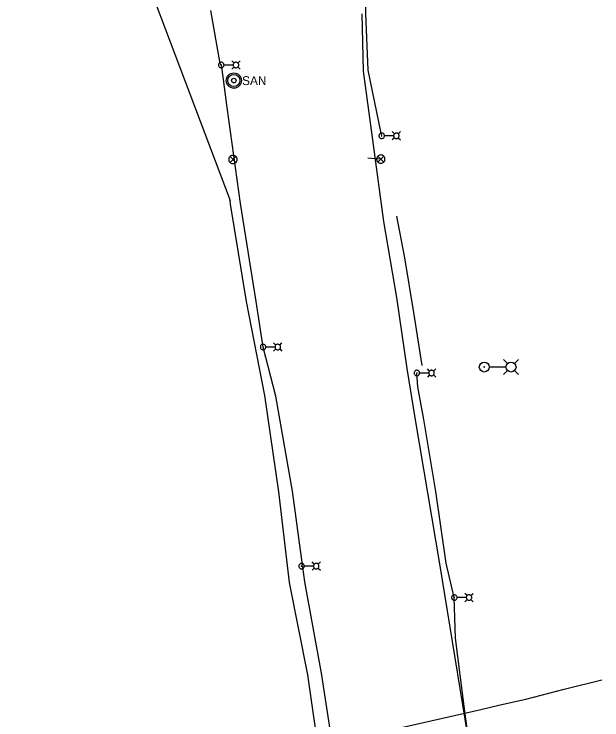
# Model space of a CAD drawing. Extents: x 600849 to 606371, y 330010 to 403088.
# Drawn here: x 604365 to 604830, y 336784 to 337341 of the extents above; entities that cross this region are included whole.
import ezdxf

# ---------------------------------------------------------------- set-up
doc = ezdxf.new("R2010")
doc.units = 0
for name, color, linetype in [('E_FTMS_Conduit', 7, 'Continuous'), ('E_LTG', 7, 'Continuous'), ('E_LTG_CID', 7, 'Continuous'), ('E_SIG', 7, 'Continuous'), ('E_UTL_E_UG', 7, 'Continuous'), ('E_UTL_FO_UG_QWEST', 7, 'Continuous'), ('E_UTL_G_UG', 7, 'Continuous'), ('E_UTL_SAN', 7, 'Continuous')]:
    doc.layers.add(name, color=color, linetype=linetype)

msp = doc.modelspace()

# ---------------------------------------------------------------- linework, layer by layer
at = {"layer": 'E_FTMS_Conduit'}
for points in [[(604787.77, 336403.56), (604778.06, 336454.77), (604767.68, 336514.34), (604755.05, 336571.74), (604744.37, 336629.18), (604737.87, 336681.73), (604730.03, 336734.18), (604701.87, 336906.78), (604692.35, 336962.82), (604682.52, 337020.66), (604676.08, 337061.02), (604667.84, 337117.16), (604657.46, 337177.3), (604649.41, 337237.66), (604641.55, 337295.97), (604640.55, 337341.15)], [(604667.53, 337181.51), (604673.81, 337148.58), (604680.95, 337105.47), (604687.63, 337063.48)]]:
    msp.add_lwpolyline(points, dxfattribs=at)
at = {"layer": 'E_LTG'}
for points in [[(604531.31, 337300.78), (604531.27, 337301.19), (604531.15, 337301.59), (604530.96, 337301.95), (604530.7, 337302.28), (604530.39, 337302.55), (604530.03, 337302.76), (604529.64, 337302.89), (604529.23, 337302.95), (604528.82, 337302.93), (604528.42, 337302.83), (604528.04, 337302.66), (604527.71, 337302.42), (604527.42, 337302.12), (604527.2, 337301.78), (604527.04, 337301.39), (604526.96, 337300.99), (604526.96, 337300.57), (604527.04, 337300.17), (604527.2, 337299.78), (604527.42, 337299.43), (604527.71, 337299.13), (604528.04, 337298.89), (604528.42, 337298.72), (604528.82, 337298.62), (604529.23, 337298.61), (604529.64, 337298.66), (604530.03, 337298.8), (604530.39, 337299.01), (604530.7, 337299.28), (604530.96, 337299.6), (604531.15, 337299.97), (604531.27, 337300.37), (604531.31, 337300.78)], [(604539.21, 337302.3), (604537.43, 337304.08)], [(604542.91, 337300.78), (604542.87, 337301.19), (604542.75, 337301.59), (604542.56, 337301.95), (604542.31, 337302.28), (604542, 337302.55), (604541.64, 337302.76), (604541.25, 337302.89), (604540.84, 337302.95), (604540.42, 337302.93), (604540.02, 337302.83), (604539.65, 337302.66), (604539.31, 337302.42), (604539.02, 337302.12), (604538.8, 337301.78), (604538.65, 337301.39), (604538.57, 337300.99), (604538.57, 337300.57), (604538.65, 337300.17), (604538.8, 337299.78), (604539.02, 337299.43), (604539.31, 337299.13), (604539.65, 337298.89), (604540.02, 337298.72), (604540.42, 337298.62), (604540.84, 337298.61), (604541.25, 337298.66), (604541.64, 337298.8), (604542, 337299.01), (604542.31, 337299.28), (604542.56, 337299.6), (604542.75, 337299.97), (604542.87, 337300.37), (604542.91, 337300.78)], [(604542.26, 337302.3), (604544.03, 337304.08)], [(604529.3, 337300.78), (604529.29, 337300.81), (604529.28, 337300.84), (604529.27, 337300.87), (604529.25, 337300.89), (604529.23, 337300.91), (604529.2, 337300.93), (604529.17, 337300.94), (604529.14, 337300.94), (604529.11, 337300.94), (604529.08, 337300.94), (604529.05, 337300.92), (604529.02, 337300.9), (604529, 337300.88), (604528.98, 337300.85), (604528.97, 337300.83), (604528.96, 337300.79), (604528.96, 337300.76), (604528.97, 337300.73), (604528.98, 337300.7), (604529, 337300.68), (604529.02, 337300.65), (604529.05, 337300.63), (604529.08, 337300.62), (604529.11, 337300.61), (604529.14, 337300.61), (604529.17, 337300.62), (604529.2, 337300.63), (604529.23, 337300.64), (604529.25, 337300.66), (604529.27, 337300.69), (604529.28, 337300.72), (604529.29, 337300.75), (604529.3, 337300.78)], [(604538.52, 337300.78), (604531.34, 337300.78)], [(604539.21, 337299.26), (604537.43, 337297.48)], [(604542.26, 337299.26), (604544.03, 337297.48)], [(604658.04, 337244.87), (604658, 337245.28), (604657.88, 337245.68), (604657.69, 337246.04), (604657.44, 337246.37), (604657.12, 337246.64), (604656.76, 337246.85), (604656.37, 337246.98), (604655.96, 337247.04), (604655.55, 337247.02), (604655.15, 337246.92), (604654.77, 337246.75), (604654.44, 337246.51), (604654.15, 337246.21), (604653.93, 337245.87), (604653.77, 337245.48), (604653.69, 337245.08), (604653.69, 337244.66), (604653.77, 337244.26), (604653.93, 337243.87), (604654.15, 337243.52), (604654.44, 337243.22), (604654.77, 337242.98), (604655.15, 337242.81), (604655.55, 337242.71), (604655.96, 337242.7), (604656.37, 337242.75), (604656.76, 337242.89), (604657.12, 337243.1), (604657.44, 337243.37), (604657.69, 337243.69), (604657.88, 337244.06), (604658, 337244.46), (604658.04, 337244.87)], [(604665.94, 337246.39), (604664.16, 337248.17)], [(604669.64, 337244.87), (604669.6, 337245.28), (604669.48, 337245.68), (604669.29, 337246.04), (604669.04, 337246.37), (604668.73, 337246.64), (604668.37, 337246.85), (604667.98, 337246.98), (604667.57, 337247.04), (604667.15, 337247.02), (604666.75, 337246.92), (604666.38, 337246.75), (604666.04, 337246.51), (604665.75, 337246.21), (604665.53, 337245.87), (604665.38, 337245.48), (604665.3, 337245.08), (604665.3, 337244.66), (604665.38, 337244.26), (604665.53, 337243.87), (604665.75, 337243.52), (604666.04, 337243.22), (604666.38, 337242.98), (604666.75, 337242.81), (604667.15, 337242.71), (604667.57, 337242.7), (604667.98, 337242.75), (604668.37, 337242.89), (604668.73, 337243.1), (604669.04, 337243.37), (604669.29, 337243.69), (604669.48, 337244.06), (604669.6, 337244.46), (604669.64, 337244.87)], [(604668.99, 337246.39), (604670.77, 337248.17)], [(604656.03, 337244.87), (604656.02, 337244.9), (604656.02, 337244.93), (604656, 337244.96), (604655.98, 337244.98), (604655.96, 337245), (604655.93, 337245.02), (604655.9, 337245.03), (604655.87, 337245.03), (604655.84, 337245.03), (604655.81, 337245.03), (604655.78, 337245.01), (604655.75, 337244.99), (604655.73, 337244.97), (604655.71, 337244.94), (604655.7, 337244.92), (604655.69, 337244.88), (604655.69, 337244.85), (604655.7, 337244.82), (604655.71, 337244.79), (604655.73, 337244.77), (604655.75, 337244.74), (604655.78, 337244.72), (604655.81, 337244.71), (604655.84, 337244.7), (604655.87, 337244.7), (604655.9, 337244.71), (604655.93, 337244.72), (604655.96, 337244.73), (604655.98, 337244.75), (604656, 337244.78), (604656.02, 337244.81), (604656.02, 337244.84), (604656.03, 337244.87)], [(604665.25, 337244.87), (604658.07, 337244.87)], [(604665.94, 337243.35), (604664.16, 337241.57)], [(604668.99, 337243.35), (604670.77, 337241.57)], [(604564.33, 337078.06), (604564.29, 337078.48), (604564.17, 337078.87), (604563.99, 337079.24), (604563.73, 337079.57), (604563.42, 337079.84), (604563.06, 337080.04), (604562.67, 337080.18), (604562.26, 337080.24), (604561.85, 337080.22), (604561.44, 337080.12), (604561.07, 337079.95), (604560.73, 337079.71), (604560.44, 337079.41), (604560.22, 337079.06), (604560.07, 337078.68), (604559.99, 337078.27), (604559.99, 337077.86), (604560.07, 337077.45), (604560.22, 337077.07), (604560.44, 337076.72), (604560.73, 337076.42), (604561.07, 337076.18), (604561.44, 337076.01), (604561.85, 337075.91), (604562.26, 337075.89), (604562.67, 337075.95), (604563.06, 337076.09), (604563.42, 337076.29), (604563.73, 337076.56), (604563.99, 337076.89), (604564.17, 337077.26), (604564.29, 337077.65), (604564.33, 337078.06)], [(604572.24, 337079.59), (604570.46, 337081.37)], [(604575.93, 337078.06), (604575.89, 337078.48), (604575.78, 337078.87), (604575.59, 337079.24), (604575.33, 337079.57), (604575.02, 337079.84), (604574.66, 337080.04), (604574.27, 337080.18), (604573.86, 337080.24), (604573.45, 337080.22), (604573.05, 337080.12), (604572.67, 337079.95), (604572.33, 337079.71), (604572.05, 337079.41), (604571.82, 337079.06), (604571.67, 337078.68), (604571.59, 337078.27), (604571.59, 337077.86), (604571.67, 337077.45), (604571.82, 337077.07), (604572.05, 337076.72), (604572.33, 337076.42), (604572.67, 337076.18), (604573.05, 337076.01), (604573.45, 337075.91), (604573.86, 337075.89), (604574.27, 337075.95), (604574.66, 337076.09), (604575.02, 337076.29), (604575.33, 337076.56), (604575.59, 337076.89), (604575.78, 337077.26), (604575.89, 337077.65), (604575.93, 337078.06)], [(604575.28, 337079.59), (604577.06, 337081.37)], [(604562.32, 337078.06), (604562.32, 337078.1), (604562.31, 337078.13), (604562.29, 337078.15), (604562.28, 337078.18), (604562.25, 337078.2), (604562.22, 337078.22), (604562.19, 337078.23), (604562.16, 337078.23), (604562.13, 337078.23), (604562.1, 337078.22), (604562.07, 337078.21), (604562.05, 337078.19), (604562.02, 337078.17), (604562.01, 337078.14), (604562, 337078.11), (604561.99, 337078.08), (604561.99, 337078.05), (604562, 337078.02), (604562.01, 337077.99), (604562.02, 337077.96), (604562.05, 337077.94), (604562.07, 337077.92), (604562.1, 337077.91), (604562.13, 337077.9), (604562.16, 337077.9), (604562.19, 337077.9), (604562.22, 337077.91), (604562.25, 337077.93), (604562.28, 337077.95), (604562.29, 337077.97), (604562.31, 337078), (604562.32, 337078.03), (604562.32, 337078.06)], [(604571.55, 337078.07), (604564.37, 337078.07)], [(604572.24, 337076.54), (604570.46, 337074.77)], [(604575.28, 337076.54), (604577.06, 337074.77)], [(604755.23, 337065.06), (604752, 337068.29)], [(604760.77, 337065.06), (604764, 337068.29)], [(604685.82, 337057.55), (604685.78, 337057.96), (604685.66, 337058.36), (604685.47, 337058.73), (604685.22, 337059.05), (604684.91, 337059.32), (604684.55, 337059.53), (604684.16, 337059.66), (604683.75, 337059.72), (604683.33, 337059.7), (604682.93, 337059.61), (604682.56, 337059.43), (604682.22, 337059.19), (604681.93, 337058.89), (604681.71, 337058.55), (604681.56, 337058.16), (604681.48, 337057.76), (604681.48, 337057.34), (604681.56, 337056.94), (604681.71, 337056.55), (604681.93, 337056.2), (604682.22, 337055.91), (604682.56, 337055.67), (604682.93, 337055.49), (604683.33, 337055.4), (604683.75, 337055.38), (604684.16, 337055.44), (604684.55, 337055.57), (604684.91, 337055.78), (604685.22, 337056.05), (604685.47, 337056.37), (604685.66, 337056.74), (604685.78, 337057.14), (604685.82, 337057.55)], [(604683.81, 337057.55), (604683.81, 337057.58), (604683.8, 337057.61), (604683.78, 337057.64), (604683.76, 337057.66), (604683.74, 337057.69), (604683.71, 337057.7), (604683.68, 337057.71), (604683.65, 337057.72), (604683.62, 337057.71), (604683.59, 337057.71), (604683.56, 337057.69), (604683.53, 337057.68), (604683.51, 337057.65), (604683.5, 337057.63), (604683.48, 337057.6), (604683.48, 337057.57), (604683.48, 337057.53), (604683.48, 337057.5), (604683.5, 337057.47), (604683.51, 337057.45), (604683.53, 337057.42), (604683.56, 337057.41), (604683.59, 337057.39), (604683.62, 337057.39), (604683.65, 337057.38), (604683.68, 337057.39), (604683.71, 337057.4), (604683.74, 337057.41), (604683.76, 337057.43), (604683.78, 337057.46), (604683.8, 337057.49), (604683.81, 337057.52), (604683.81, 337057.55)], [(604693.03, 337057.55), (604685.86, 337057.55)], [(604693.72, 337059.08), (604691.95, 337060.85)], [(604697.42, 337057.55), (604697.38, 337057.96), (604697.27, 337058.36), (604697.08, 337058.73), (604696.82, 337059.05), (604696.51, 337059.32), (604696.15, 337059.53), (604695.76, 337059.66), (604695.35, 337059.72), (604694.94, 337059.7), (604694.54, 337059.61), (604694.16, 337059.43), (604693.82, 337059.19), (604693.54, 337058.89), (604693.31, 337058.55), (604693.16, 337058.16), (604693.08, 337057.76), (604693.08, 337057.34), (604693.16, 337056.94), (604693.31, 337056.55), (604693.54, 337056.2), (604693.82, 337055.91), (604694.16, 337055.67), (604694.54, 337055.49), (604694.94, 337055.4), (604695.35, 337055.38), (604695.76, 337055.44), (604696.15, 337055.57), (604696.51, 337055.78), (604696.82, 337056.05), (604697.08, 337056.37), (604697.27, 337056.74), (604697.38, 337057.14), (604697.42, 337057.55)], [(604696.77, 337059.08), (604698.55, 337060.85)], [(604753.98, 337062.29), (604740.93, 337062.29)], [(604755.23, 337059.52), (604752, 337056.29)], [(604760.77, 337059.52), (604764, 337056.29)], [(604693.72, 337056.03), (604691.95, 337054.25)], [(604696.77, 337056.03), (604698.55, 337054.25)], [(604594.7, 336905.04), (604594.66, 336905.45), (604594.54, 336905.84), (604594.35, 336906.21), (604594.1, 336906.54), (604593.79, 336906.81), (604593.43, 336907.01), (604593.04, 336907.15), (604592.63, 336907.21), (604592.21, 336907.19), (604591.81, 336907.09), (604591.44, 336906.92), (604591.1, 336906.68), (604590.81, 336906.38), (604590.59, 336906.03), (604590.44, 336905.65), (604590.36, 336905.24), (604590.36, 336904.83), (604590.44, 336904.42), (604590.59, 336904.04), (604590.81, 336903.69), (604591.1, 336903.39), (604591.44, 336903.15), (604591.81, 336902.98), (604592.21, 336902.88), (604592.63, 336902.86), (604593.04, 336902.92), (604593.43, 336903.06), (604593.79, 336903.26), (604594.1, 336903.53), (604594.35, 336903.86), (604594.54, 336904.23), (604594.66, 336904.62), (604594.7, 336905.04)], [(604602.61, 336906.56), (604600.83, 336908.34)], [(604606.3, 336905.04), (604606.26, 336905.45), (604606.15, 336905.84), (604605.96, 336906.21), (604605.7, 336906.54), (604605.39, 336906.81), (604605.03, 336907.01), (604604.64, 336907.15), (604604.23, 336907.21), (604603.82, 336907.19), (604603.42, 336907.09), (604603.04, 336906.92), (604602.7, 336906.68), (604602.42, 336906.38), (604602.19, 336906.03), (604602.04, 336905.65), (604601.96, 336905.24), (604601.96, 336904.83), (604602.04, 336904.42), (604602.19, 336904.04), (604602.42, 336903.69), (604602.7, 336903.39), (604603.04, 336903.15), (604603.42, 336902.98), (604603.82, 336902.88), (604604.23, 336902.86), (604604.64, 336902.92), (604605.03, 336903.06), (604605.39, 336903.26), (604605.7, 336903.53), (604605.96, 336903.86), (604606.15, 336904.23), (604606.26, 336904.62), (604606.3, 336905.04)], [(604605.65, 336906.56), (604607.43, 336908.34)], [(604592.69, 336905.04), (604592.69, 336905.07), (604592.68, 336905.1), (604592.66, 336905.13), (604592.64, 336905.15), (604592.62, 336905.17), (604592.59, 336905.19), (604592.56, 336905.2), (604592.53, 336905.2), (604592.5, 336905.2), (604592.47, 336905.19), (604592.44, 336905.18), (604592.41, 336905.16), (604592.39, 336905.14), (604592.38, 336905.11), (604592.36, 336905.08), (604592.36, 336905.05), (604592.36, 336905.02), (604592.36, 336904.99), (604592.38, 336904.96), (604592.39, 336904.93), (604592.41, 336904.91), (604592.44, 336904.89), (604592.47, 336904.88), (604592.5, 336904.87), (604592.53, 336904.87), (604592.56, 336904.87), (604592.59, 336904.88), (604592.62, 336904.9), (604592.64, 336904.92), (604592.66, 336904.95), (604592.68, 336904.97), (604592.69, 336905), (604592.69, 336905.04)], [(604601.91, 336905.04), (604594.74, 336905.04)], [(604602.61, 336903.51), (604600.83, 336901.74)], [(604605.65, 336903.51), (604607.43, 336901.74)], [(604715.4, 336880.26), (604715.36, 336880.68), (604715.24, 336881.07), (604715.05, 336881.44), (604714.79, 336881.77), (604714.48, 336882.04), (604714.12, 336882.24), (604713.73, 336882.38), (604713.32, 336882.44), (604712.91, 336882.42), (604712.51, 336882.32), (604712.13, 336882.15), (604711.79, 336881.91), (604711.51, 336881.61), (604711.29, 336881.26), (604711.13, 336880.88), (604711.05, 336880.47), (604711.05, 336880.06), (604711.13, 336879.65), (604711.29, 336879.27), (604711.51, 336878.92), (604711.79, 336878.62), (604712.13, 336878.38), (604712.51, 336878.21), (604712.91, 336878.11), (604713.32, 336878.09), (604713.73, 336878.15), (604714.12, 336878.29), (604714.48, 336878.49), (604714.79, 336878.76), (604715.05, 336879.09), (604715.24, 336879.46), (604715.36, 336879.85), (604715.4, 336880.26)], [(604713.39, 336880.26), (604713.38, 336880.3), (604713.37, 336880.33), (604713.36, 336880.35), (604713.34, 336880.38), (604713.32, 336880.4), (604713.29, 336880.42), (604713.26, 336880.43), (604713.23, 336880.43), (604713.2, 336880.43), (604713.17, 336880.42), (604713.14, 336880.41), (604713.11, 336880.39), (604713.09, 336880.37), (604713.07, 336880.34), (604713.06, 336880.31), (604713.05, 336880.28), (604713.05, 336880.25), (604713.06, 336880.22), (604713.07, 336880.19), (604713.09, 336880.16), (604713.11, 336880.14), (604713.14, 336880.12), (604713.17, 336880.11), (604713.2, 336880.1), (604713.23, 336880.1), (604713.26, 336880.1), (604713.29, 336880.11), (604713.32, 336880.13), (604713.34, 336880.15), (604713.36, 336880.17), (604713.37, 336880.2), (604713.38, 336880.23), (604713.39, 336880.26)], [(604722.61, 336880.26), (604715.43, 336880.26)], [(604723.3, 336881.79), (604721.52, 336883.56)], [(604727, 336880.26), (604726.96, 336880.68), (604726.84, 336881.07), (604726.65, 336881.44), (604726.4, 336881.77), (604726.08, 336882.04), (604725.73, 336882.24), (604725.34, 336882.38), (604724.93, 336882.44), (604724.51, 336882.42), (604724.11, 336882.32), (604723.74, 336882.15), (604723.4, 336881.91), (604723.11, 336881.61), (604722.89, 336881.26), (604722.74, 336880.88), (604722.66, 336880.47), (604722.66, 336880.06), (604722.74, 336879.65), (604722.89, 336879.27), (604723.11, 336878.92), (604723.4, 336878.62), (604723.74, 336878.38), (604724.11, 336878.21), (604724.51, 336878.11), (604724.93, 336878.09), (604725.34, 336878.15), (604725.73, 336878.29), (604726.08, 336878.49), (604726.4, 336878.76), (604726.65, 336879.09), (604726.84, 336879.46), (604726.96, 336879.85), (604727, 336880.26)], [(604726.35, 336881.79), (604728.12, 336883.56)], [(604723.3, 336878.74), (604721.52, 336876.96)], [(604726.35, 336878.74), (604728.12, 336876.96)]]:
    msp.add_lwpolyline(points, dxfattribs=at)
for centre, radius in [((604736.9, 337062.29), 3.96), ((604758, 337062.29), 3.96), ((604736.9, 337062.29), 0.303)]:
    msp.add_circle(centre, radius, dxfattribs=at)
at = {"layer": 'E_LTG_CID'}
for points in [[(604655.86, 337244.87), (604655.45, 337247.07), (604645.16, 337296.66), (604643.23, 337341.37), (604642.94, 337396.12), (604631.14, 337443.78), (604627.33, 337447.68), (604626.49, 337452.83), (604621.02, 337506.96), (604614.49, 337562.63), (604607.69, 337608.04), (604595.35, 337637.29), (604593.26, 337646.33), (604591.86, 337662.02), (604588.47, 337689.68), (604582.79, 337721.06), (604569.75, 337774.7), (604568.46, 337780.5), (604568.39, 337781.64)], [(604615.78, 336772.5), (604608.22, 336820.59), (604595.1, 336892.72), (604593.66, 336904.12), (604592.52, 336905.04), (604593.4, 336906.12), (604585.34, 336964.27), (604572.19, 337039.33), (604562.15, 337078.06), (604556.73, 337113.97), (604544.3, 337191.39), (604533.74, 337267.32), (604529.63, 337299.25), (604528.37, 337301.98), (604520.87, 337343.77)], [(604791.67, 336404.29), (604783.31, 336455.52), (604771.22, 336515.74), (604772.73, 336522.21), (604758.88, 336572.41), (604748.05, 336629.75), (604738.79, 336682.15), (604736.01, 336701.86), (604729.06, 336733.74), (604721.18, 336792.28), (604714.09, 336848.09), (604713.22, 336880.26), (604706.86, 336907.31), (604698.49, 336963.96), (604689.23, 337020.9), (604684.41, 337046.52), (604683.64, 337057.55)]]:
    msp.add_lwpolyline(points, dxfattribs=at)
at = {"layer": 'E_SIG'}
for points in [[(604541.67, 337226.17), (604541.61, 337226.8), (604541.44, 337227.4), (604541.15, 337227.96), (604540.76, 337228.45), (604540.29, 337228.86), (604539.74, 337229.17), (604539.15, 337229.38), (604538.53, 337229.47), (604537.9, 337229.44), (604537.29, 337229.29), (604536.72, 337229.03), (604536.21, 337228.67), (604535.78, 337228.21), (604535.44, 337227.68), (604535.21, 337227.1), (604535.09, 337226.49), (604535.09, 337225.86), (604535.21, 337225.24), (604535.44, 337224.66), (604535.78, 337224.13), (604536.21, 337223.68), (604536.72, 337223.31), (604537.29, 337223.05), (604537.9, 337222.91), (604538.53, 337222.88), (604539.15, 337222.97), (604539.74, 337223.17), (604540.29, 337223.48), (604540.76, 337223.89), (604541.15, 337224.39), (604541.44, 337224.95), (604541.61, 337225.55), (604541.67, 337226.17)], [(604540.63, 337228.51), (604536.02, 337223.85)], [(604536.02, 337228.46), (604540.68, 337223.81)], [(604658.46, 337226.45), (604658.4, 337227.07), (604658.22, 337227.67), (604657.93, 337228.23), (604657.55, 337228.72), (604657.07, 337229.14), (604656.53, 337229.45), (604655.93, 337229.65), (604655.31, 337229.74), (604654.69, 337229.71), (604654.08, 337229.57), (604653.51, 337229.31), (604653, 337228.94), (604652.56, 337228.49), (604652.22, 337227.96), (604651.99, 337227.38), (604651.87, 337226.76), (604651.87, 337226.13), (604651.99, 337225.52), (604652.22, 337224.94), (604652.56, 337224.41), (604653, 337223.95), (604653.51, 337223.59), (604654.08, 337223.33), (604654.69, 337223.18), (604655.31, 337223.15), (604655.93, 337223.24), (604656.53, 337223.45), (604657.07, 337223.76), (604657.55, 337224.17), (604657.93, 337224.66), (604658.22, 337225.22), (604658.4, 337225.82), (604658.46, 337226.45)], [(604657.42, 337228.78), (604652.81, 337224.12)], [(604652.81, 337228.73), (604657.46, 337224.08)]]:
    msp.add_lwpolyline(points, dxfattribs=at)
at = {"layer": 'E_UTL_E_UG'}
msp.add_lwpolyline([(604645.02, 337227.6), (604653.85, 337226.6)], dxfattribs=at)
at = {"layer": 'E_UTL_FO_UG_QWEST'}
for points in [[(604326.17, 337855.13), (604425.7, 337485.61), (604536.2, 337193.87)], [(604664.78, 336404.76), (604651.78, 336480.07), (604639.96, 336554.44), (604628.34, 336626.54), (604615.77, 336699.8), (604611.3, 336722.29), (604607.39, 336749.34), (604597.4, 336819.21), (604583.07, 336892.17), (604574.68, 336963.66), (604563.59, 337039.69), (604549.05, 337114), (604536.54, 337190.93), (604536.2, 337193.87)]]:
    msp.add_lwpolyline(points, dxfattribs=at)
at = {"layer": 'E_UTL_G_UG'}
msp.add_lwpolyline([(604491.86, 336735.03), (604512.6, 336739.58), (604535.19, 336745.4), (604570.18, 336753.53), (604602.89, 336761.89), (604603.6, 336761.83), (604612.92, 336764.38), (604623.92, 336766.78), (604734.14, 336791.97), (604749.39, 336795.42), (604769.69, 336800.11), (604799.87, 336807.83), (604829.8, 336815.27)], dxfattribs=at)
at = {"layer": 'E_UTL_SAN'}
for radius in [6, 4.8, 1.8]:
    msp.add_circle((604539.09, 337288.48), radius, dxfattribs=at)

# ---------------------------------------------------------------- texts
msp.add_text('SAN', height=6.998, dxfattribs=at).set_placement((604545.57, 337284.94))

doc.saveas('drawing.dxf')
